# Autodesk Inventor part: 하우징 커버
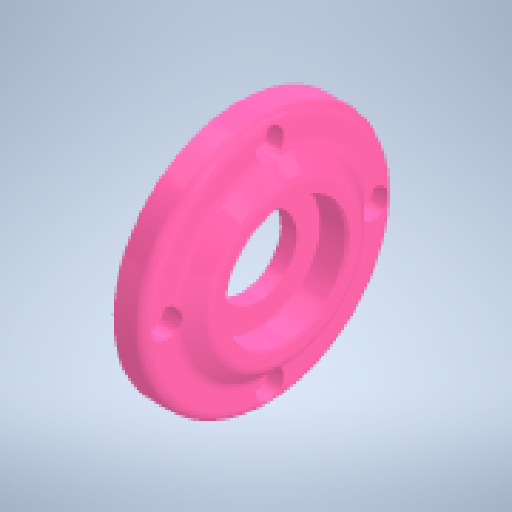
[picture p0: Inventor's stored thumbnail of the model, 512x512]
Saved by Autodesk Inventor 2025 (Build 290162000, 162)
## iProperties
Created: 2026-01
Part Number: 하우징 커버
Material: 알루미늄 6061
Document SubType Name: Modeling
Designer: KDI
Density: 2.7 g/cm^3
Appearance: 기본값
Author: jhkim
Sending System: Autodesk Inventor 2026
Preprocessor: ST-DEVELOPER v20.1
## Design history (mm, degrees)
feature "솔리드1"
node "솔리드2"
